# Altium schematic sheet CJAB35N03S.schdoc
size 127 x 101 mm
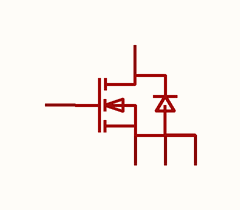
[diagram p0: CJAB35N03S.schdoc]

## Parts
Q?  cjab35n03s  [DFN-8_L3.3-W3.3-P0.65-BL-2]  (value not drawn)

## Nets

Not connected (* = marked no-connect by the designer): Q? 1(S) 2(S) 3(S) 4(G) 5(D)

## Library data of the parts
Q? = cjab35n03s: 数量:1个N沟道;漏源电压(Vdss):30V;连续漏极电流(Id):35A;导通电阻(RDS(on)):10mΩ@4.5V;耗散功率(Pd):25W;阈值电压(Vgs(th)):2.5V;; Manufacturer: CJ(江苏长电/长晶); AddInBom: yes; ModelId: 720567037d40416ca2f14c632ba061bb; ModelTransform: 129.921,130.708,0,0,0,0,0.196,33.275,0; Number: 1个N沟道; Drain to Source Voltage: 30V; Current - Continuous Drain(Id): 35A; Pd - Power Dissipation: 25W; Gate Threshold Voltage (Vgs(th)): 2.5V; Gate Charge(Qg): 24nC@10V; Input Capacitance(Ciss): 1.1nF; Reverse Transfer Capacitance (Crss@Vds): 143pF; Type: N沟道; Output Capacitance(Coss): 174pF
